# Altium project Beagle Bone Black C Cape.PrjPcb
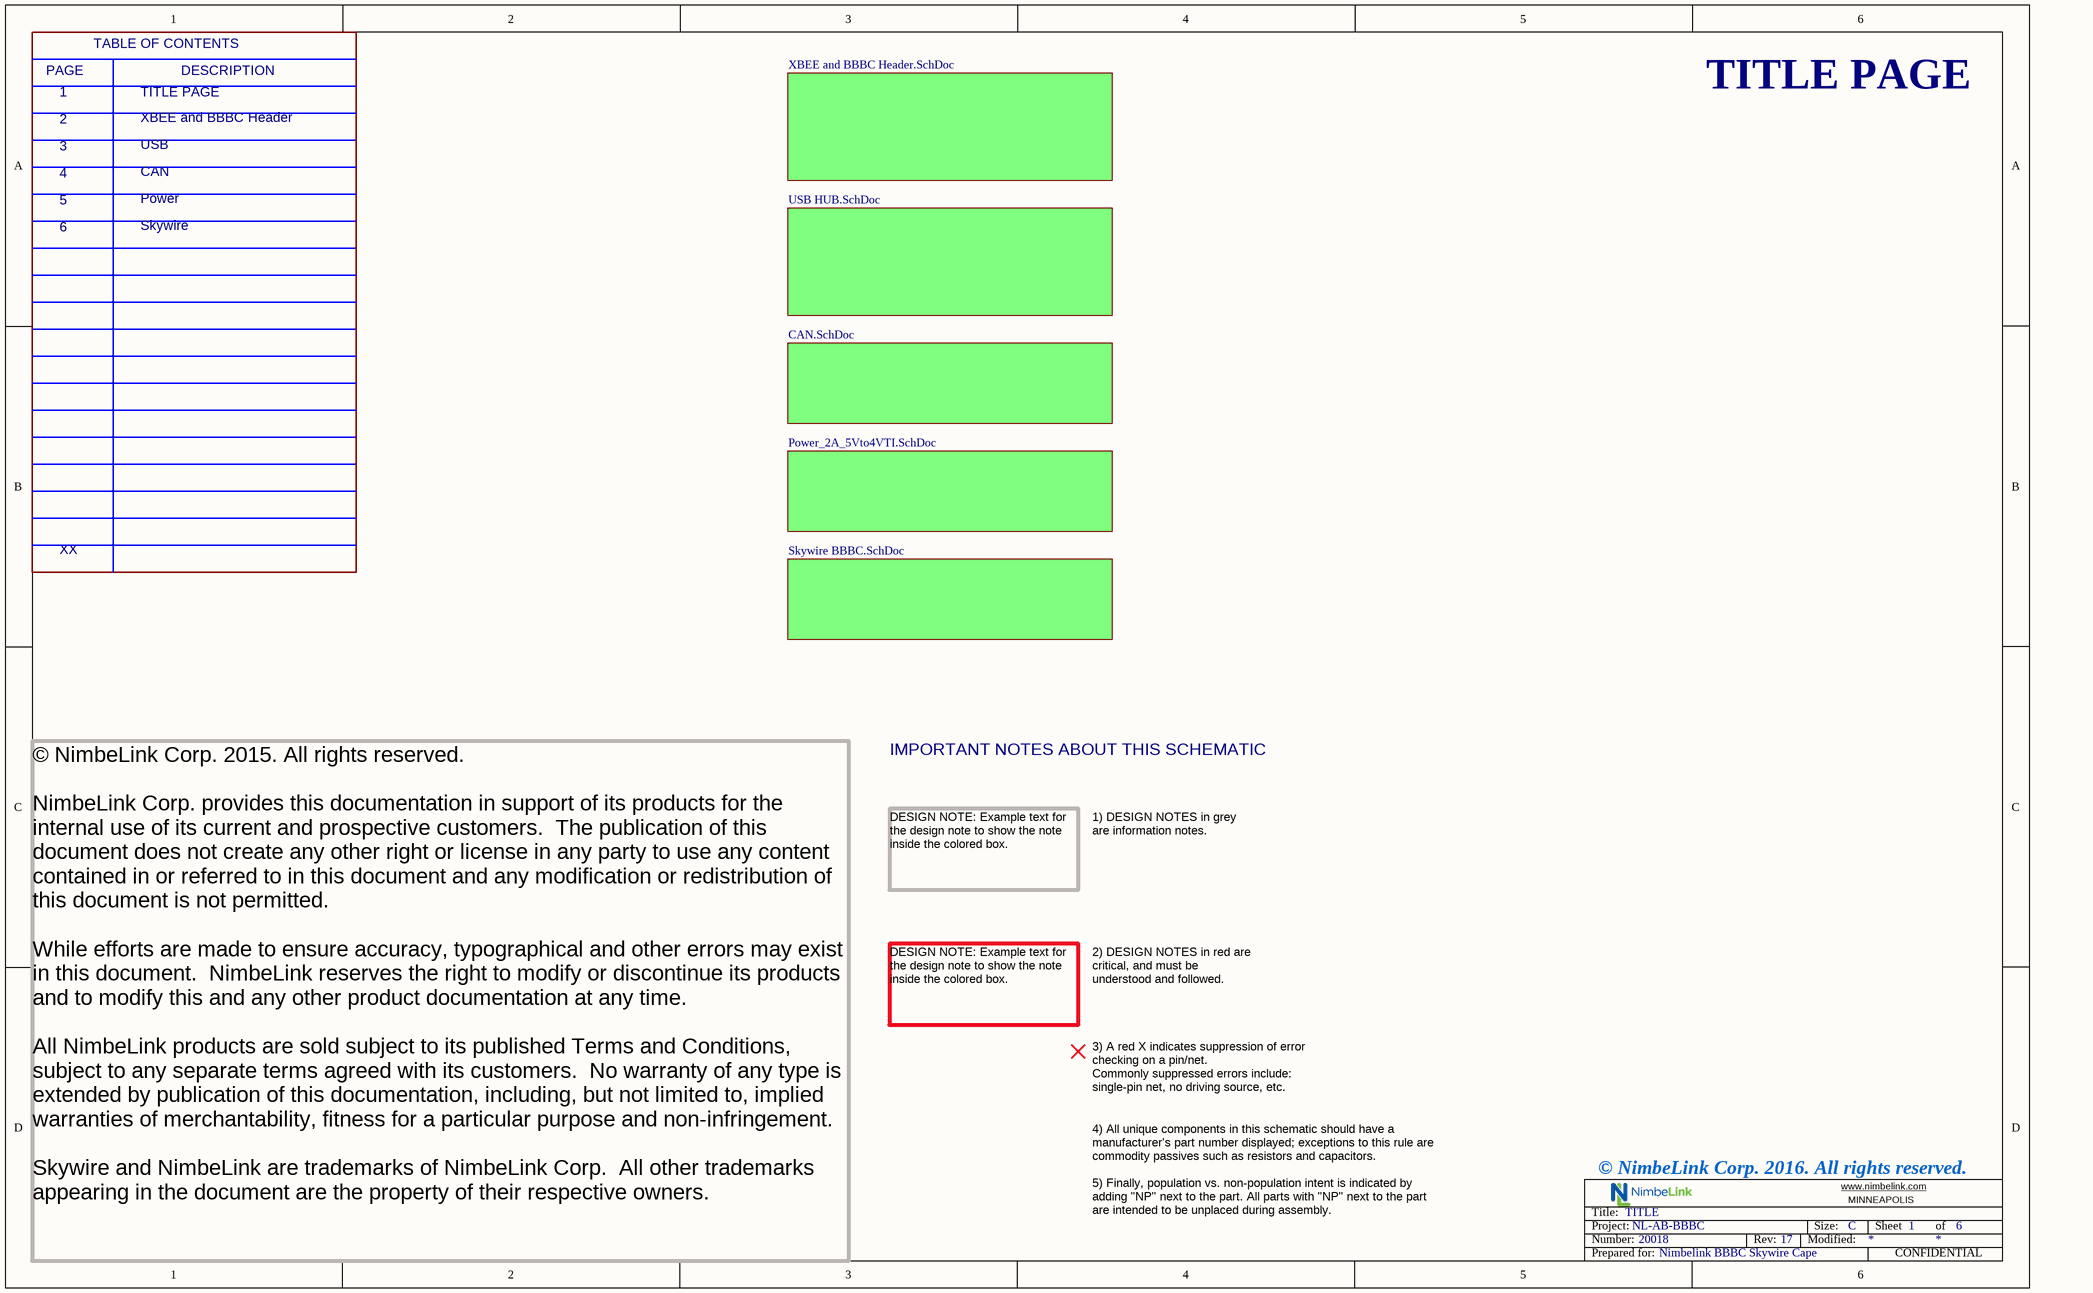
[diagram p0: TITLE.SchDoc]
NL_BILLING_CODE: NL-AB-BBBC; NL_SCH_PN: 20018; NL_SCH_REV: 17; NL_VERBOSE_CUST_NAME: Nimbelink BBBC Skywire Cape
6 sheets, 182 parts. Net scope: flat (ports and power ports of the same name join across sheets).
Board file: 20018REVE.PcbDoc
Sheets:
  TITLE.SchDoc
     = USB HUB.SchDoc
     = XBEE and BBBC Header.SchDoc
     = CAN.SchDoc
     = Power_2A_5Vto4VTI.SchDoc
     = Skywire BBBC.SchDoc

## Sheet TITLE.SchDoc: TITLE
size B; SheetNumber: 1; SheetTotal: 6

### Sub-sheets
? = USB HUB.SchDoc: no entries
? = XBEE and BBBC Header.SchDoc: no entries
? = CAN.SchDoc: no entries
? = Power_2A_5Vto4VTI.SchDoc: no entries
? = Skywire BBBC.SchDoc: no entries

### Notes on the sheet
- PAGE
- 1
- TABLE OF CONTENTS
- TITLE PAGE
- DESCRIPTION
- 2
- 3
- XBEE and BBBC Header
- USB
- 4
- 5
- 6
- Skywire
- Power
- CAN
- XX
- IMPORTANT NOTES ABOUT THIS SCHEMATIC
- DESIGN NOTE: Example text for the design note to show the note inside the colored box.
- 1) DESIGN NOTES in grey are information notes.
- 2) DESIGN NOTES in red are critical, and must be understood and followed.
- 3) A red X indicates suppression of error checking on a pin/net.
  Commonly suppressed errors include: single-pin net, no driving source, etc.
- © NimbeLink Corp. 2016. All rights reserved.
- 4) All unique components in this schematic should have a manufacturer's part number displayed; exceptions to this rule are commodity passives such as resistors and capacitors.
  5) Finally, population vs. non-population intent is indicated by adding "NP" next to the part. All parts with "NP" next to the part are intended to be unplaced during assembly.
- © NimbeLink Corp. 2015. All rights reserved.
  NimbeLink Corp. provides this documentation in support of its products for the internal use of its current and prospective customers.  The publication of this document does not create any other right or license in any party to use any content contained in or referred to in this document and any modification or redistribution of this document is not permitted.
  While efforts are made to ensure accuracy, typographical and other errors may exist in this document.  NimbeLink reserves the right to modify or discontinue its products and to modify this and any other product documentation at any time.
  All NimbeLink products are sold subject to its published Terms and Conditions, subject to any separate terms agreed with its customers.  No warranty of any type is extended by publication of this documentation, including, but not limited to, implied warranties of merchantability, fitness for a particular purpose and non-infringement.
  Skywire and NimbeLink are trademarks of NimbeLink Corp.  All other trademarks appearing in the document are the property of their respective owners.

## Sheet USB HUB.SchDoc: USB
size B; SheetNumber: 3; SheetTotal: 6
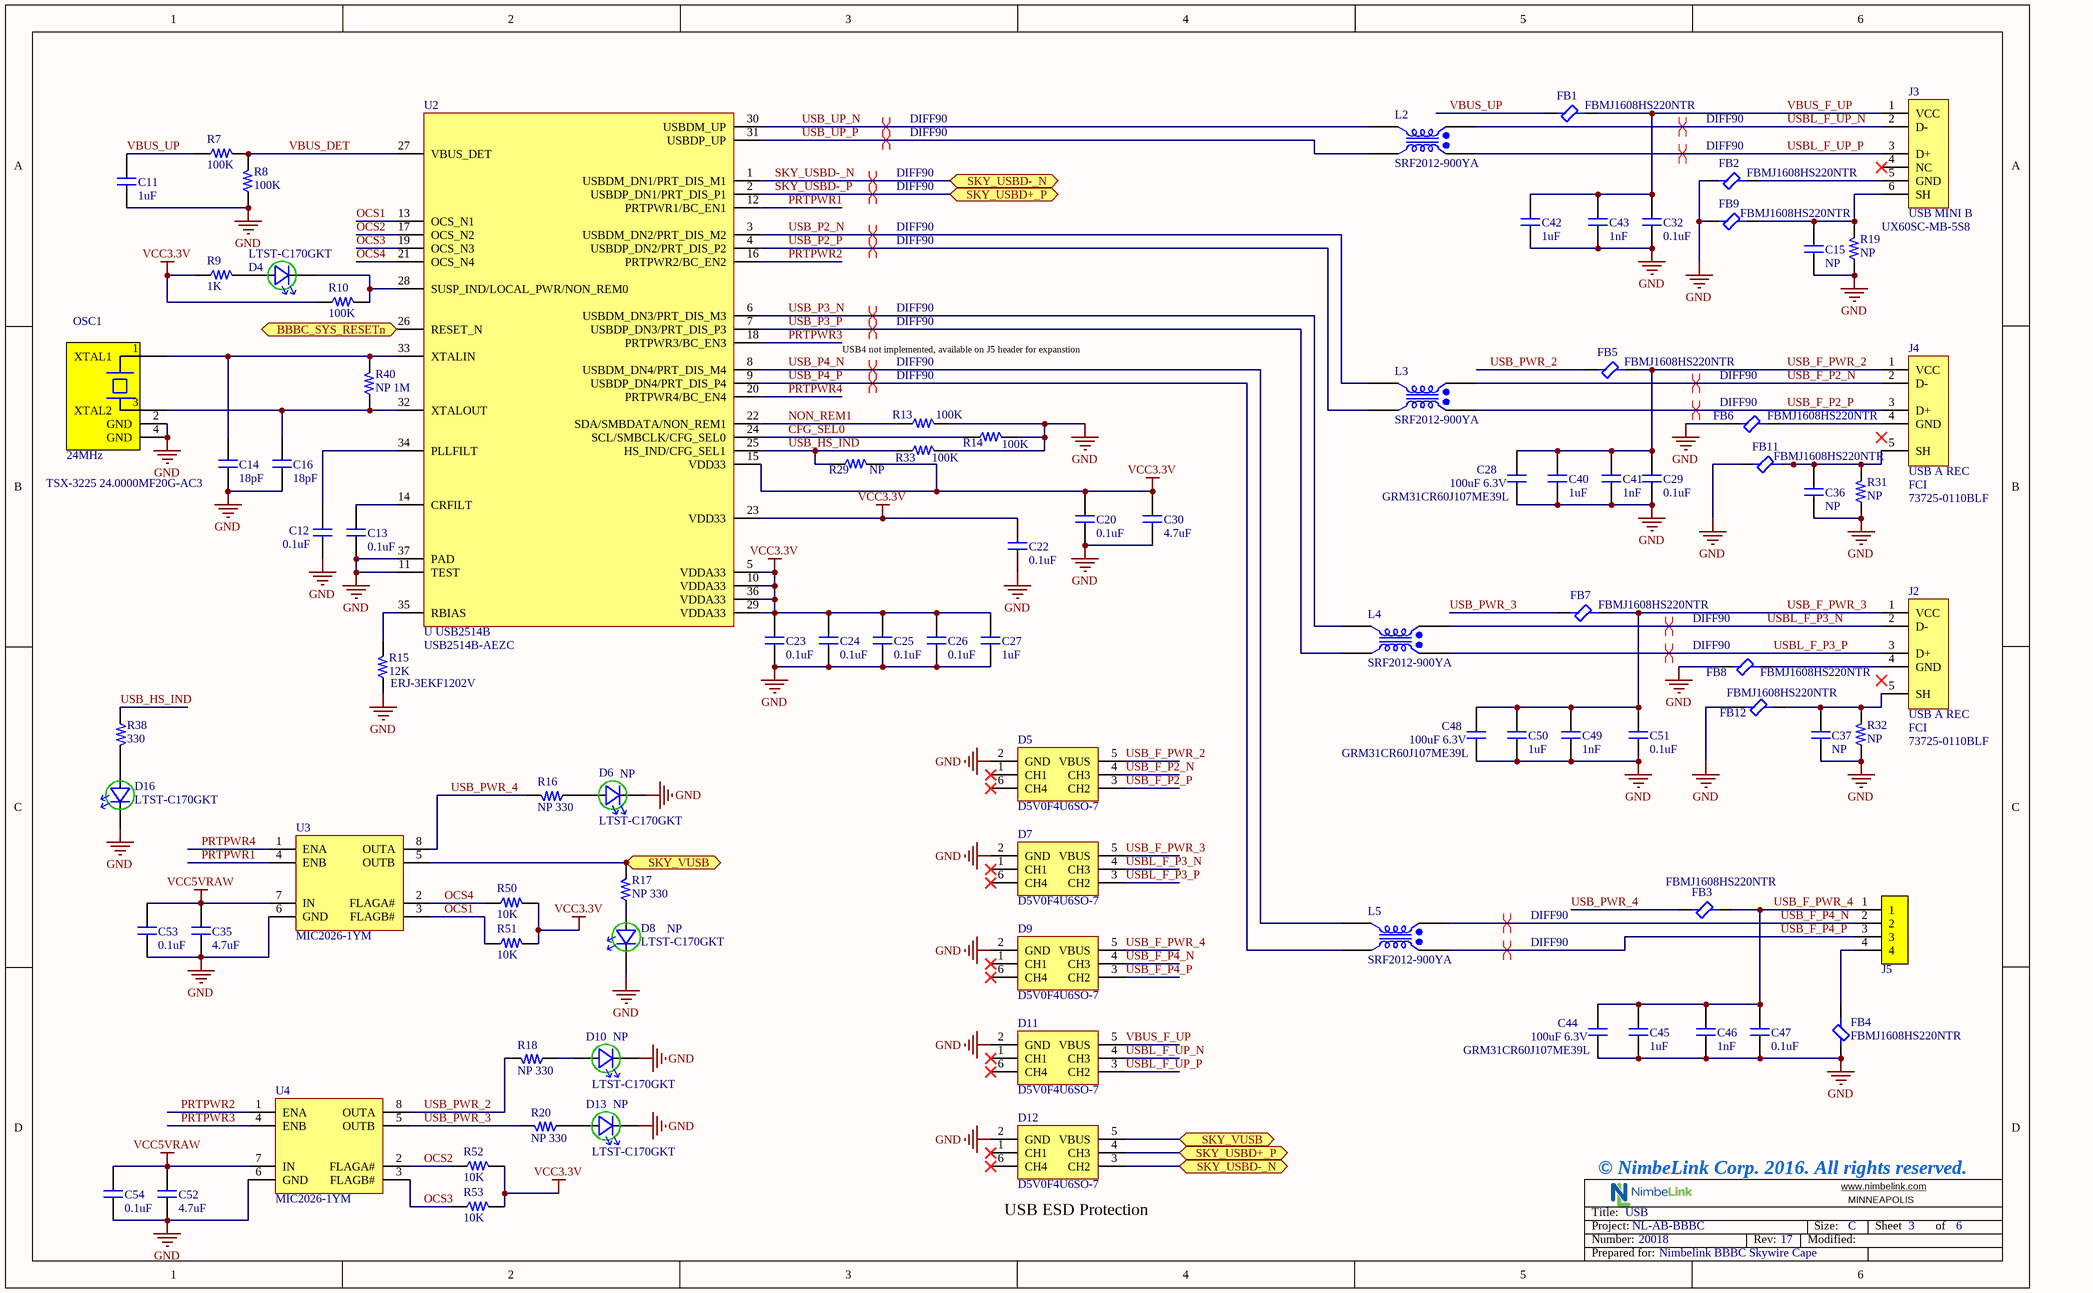
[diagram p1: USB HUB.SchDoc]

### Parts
C11  1uF  [0603]
C12  0.1uF  [0603]
C13  0.1uF  [0603]
C14  18pF  [0603]
C15  NP  [0603]
C16  18pF  [0603]
C20  0.1uF  [0603]
C22  0.1uF  [0603]
C23  0.1uF  [0603]
C24  0.1uF  [0603]
C25  0.1uF  [0603]
C26  0.1uF  [0603]
C27  1uF  [0603]
C28  100uF 6.3V  Manufacturer Part Number 1: GRM31CR60J107ME39L  [1206]
C29  0.1uF  [0603]
C30  4.7uF  [0603]
C32  0.1uF  [0603]
C35  4.7uF  [0603]
C36  NP  [0603]
C37  NP  [0603]
C40  1uF  [0603]
C41  1nF  [0603]
C42  1uF  [0603]
C43  1nF  [0603]
C44  100uF 6.3V  Manufacturer Part Number 1: GRM31CR60J107ME39L  [1206]
C45  1uF  [0603]
C46  1nF  [0603]
C47  0.1uF  [0603]
C48  100uF 6.3V  Manufacturer Part Number 1: GRM31CR60J107ME39L  [1206]
C49  1nF  [0603]
C50  1uF  [0603]
C51  0.1uF  [0603]
C52  4.7uF  [0603]
C53  0.1uF  [0603]
C54  0.1uF  [0603]
D4  Manufacturer Part Number 1: LTST-C170GKT  [D_LED_GREEN]  (hidden comment: D_LED_GREEN)
D5  D5V0F4U6SO-7  [D5V0F4U6SO-7]
D6  NP  Manufacturer Part Number 1: LTST-C170GKT  [D_LED_GREEN]
D7  D5V0F4U6SO-7  [D5V0F4U6SO-7]
D8  NP  Manufacturer Part Number 1: LTST-C170GKT  [D_LED_GREEN]
D9  D5V0F4U6SO-7  [D5V0F4U6SO-7]
D10  NP  Manufacturer Part Number 1: LTST-C170GKT  [D_LED_GREEN]
D11  D5V0F4U6SO-7  [D5V0F4U6SO-7]
D12  D5V0F4U6SO-7  [D5V0F4U6SO-7]
D13  NP  Manufacturer Part Number 1: LTST-C170GKT  [D_LED_GREEN]
D16  Manufacturer Part Number 1: LTST-C170GKT  [D_LED_GREEN]  (hidden comment: D_LED_GREEN)
FB1  Manufacturer Part Number 1: FBMJ1608HS220NTR  [0603]  (hidden comment: FB 7.5A 22Ohm 0.04DCR 0603)
FB2  Manufacturer Part Number 1: FBMJ1608HS220NTR  [0603]  (hidden comment: FB 7.5A 22Ohm 0.04DCR 0603)
FB3  Manufacturer Part Number 1: FBMJ1608HS220NTR  [0603]  (hidden comment: FB 7.5A 22Ohm 0.04DCR 0603)
FB4  Manufacturer Part Number 1: FBMJ1608HS220NTR  [0603]  (hidden comment: FB 7.5A 22Ohm 0.04DCR 0603)
FB5  Manufacturer Part Number 1: FBMJ1608HS220NTR  [0603]  (hidden comment: FB 7.5A 22Ohm 0.04DCR 0603)
FB6  Manufacturer Part Number 1: FBMJ1608HS220NTR  [0603]  (hidden comment: FB 7.5A 22Ohm 0.04DCR 0603)
FB7  Manufacturer Part Number 1: FBMJ1608HS220NTR  [0603]  (hidden comment: FB 7.5A 22Ohm 0.04DCR 0603)
FB8  Manufacturer Part Number 1: FBMJ1608HS220NTR  [0603]  (hidden comment: FB 7.5A 22Ohm 0.04DCR 0603)
FB9  Manufacturer Part Number 1: FBMJ1608HS220NTR  [0603]  (hidden comment: FB 7.5A 22Ohm 0.04DCR 0603)
FB11  Manufacturer Part Number 1: FBMJ1608HS220NTR  [0603]  (hidden comment: FB 7.5A 22Ohm 0.04DCR 0603)
FB12  Manufacturer Part Number 1: FBMJ1608HS220NTR  [0603]  (hidden comment: FB 7.5A 22Ohm 0.04DCR 0603)
J2  USB A REC  Manufacturer 1: FCI  Manufacturer Part Number 1: 73725-0110BLF  [USBA FCI VERT]
J3  USB MINI B  Manufacturer Part Number 1: UX60SC-MB-5S8  [USB MINI B]
J4  USB A REC  Manufacturer 1: FCI  Manufacturer Part Number 1: 73725-0110BLF  [USBA FCI VERT]
J5  NP  [HEADER 4PIN 2MMPITCH]  (value not drawn)
L2  SRF2012-900YA  [SRF2012-900YA]
L3  SRF2012-900YA  [SRF2012-900YA]
L4  SRF2012-900YA  [SRF2012-900YA]
L5  SRF2012-900YA  [SRF2012-900YA]
OSC1  24MHz  [OSC 008-0288-0_F]
R7  100K  [0603]
R8  100K  [0603]
R9  1K  [0603]
R10  100K  [0603]
R13  100K  [0603]
R14  100K  [0603]
R15  12K  Manufacturer Part Number 1: ERJ-3EKF1202V  [0603]
R16  NP 330  [0603]
R17  NP 330  [0603]
R18  NP 330  [0603]
R19  NP  [0603]
R20  NP 330  [0603]
R29  NP  [0603]
R31  NP  [0603]
R32  NP  [0603]
R33  100K  [0603]
R38  330  [0603]
R40  NP 1M  [0603]
R50  10K  [0603]
R51  10K  [0603]
R52  10K  [0603]
R53  10K  [0603]
U2  U USB2514B  Manufacturer Part Number 1: USB2514B-AEZC  [USB2514]
U3  Manufacturer Part Number 1: MIC2026-1YM  [MIC2026]  (hidden comment: U MIC2026)
U4  Manufacturer Part Number 1: MIC2026-1YM  [MIC2026]  (hidden comment: U MIC2026)

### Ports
BBBC_SYS_RESETn, SKY_USBD+_P, SKY_USBD-_N, SKY_VUSB

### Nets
GND: C11.2 C12.2 C13.2 C14.1 C15.2 C16.1 C20.2 C22.2 C23.2 C24.2 C25.2 C26.2 C27.2 C28.2 C29.2 C30.2 C32.2 C35.2 C36.2 C37.2 C40.2 C41.2 C42.2 C43.2 C44.2 C45.2 C46.2 C47.2 C48.2 C49.2 C50.2 C51.2 C52.2 C53.2 C54.2 D5.2(GND) D6.2(Cathode) D7.2(GND) D8.2(Cathode) D9.2(GND) D10.2(Cathode) D11.2(GND) D12.2(GND) D13.2(Cathode) D16.2(Cathode) FB2.1 FB4.1 FB6.1 FB8.1 FB9.1 FB11.1 FB12.1 OSC1.2(GND) OSC1.4(GND) R8.1 R13.2 R14.2 R15.1 R19.1 R31.1 R32.1 R33.2 U2.11(TEST) U2.37(PAD) U3.6(GND) U4.6(GND)
VCC3.3V: C20.1 C22.1 C23.1 C24.1 C25.1 C26.1 C27.1 C30.1 R9.1 R10.1 R29.2 R50.2 R51.2 R52.2 R53.2 U2.5(VDDA33) U2.10(VDDA33) U2.15(VDD33) U2.23(VDD33) U2.29(VDDA33) U2.36(VDDA33)
VCC5VRAW: C35.1 C52.1 C53.1 C54.1 U3.7(IN) U4.7(IN)
CFG_SEL0: R14.1 U2.24(SCL/SMBCLK/CFG_SEL0)
NON_REM1: R13.1 U2.22(SDA/SMBDATA/NON_REM1)
OCS1: R51.1 U2.13(OCS_N1) U3.3(FLAGB#)
OCS2: R52.1 U2.17(OCS_N2) U4.2(FLAGA#)
OCS3: R53.1 U2.19(OCS_N3) U4.3(FLAGB#)
OCS4: R50.1 U2.21(OCS_N4) U3.2(FLAGA#)
PRTPWR1: U2.12(PRTPWR1/BC_EN1) U3.4(ENB)
PRTPWR2: U2.16(PRTPWR2/BC_EN2) U4.1(ENA)
PRTPWR3: U2.18(PRTPWR3/BC_EN3) U4.4(ENB)
PRTPWR4: U2.20(PRTPWR4/BC_EN4) U3.1(ENA)
SKY_USBD-_N: D12.3(CH2) U2.1(USBDM_DN1/PRT_DIS_M1) ; port SKY_USBD-_N
SKY_USBD-_P: D12.4(CH3) U2.2(USBDP_DN1/PRT_DIS_P1) ; port SKY_USBD+_P
USB_F_P2_N: D5.4(CH3) J4.2(D-) L3.1
USB_F_P2_P: D5.3(CH2) J4.3(D+) L3.2
USB_F_P4_N: D9.4(CH3) J5.2 L5.1
USB_F_P4_P: D9.3(CH2) J5.3 L5.2
USB_F_PWR_2: C28.1 C29.1 C40.1 C41.1 D5.5(VBUS) FB5.2 J4.1(VCC)
USB_F_PWR_3: C48.1 C49.1 C50.1 C51.1 D7.5(VBUS) FB7.2 J2.1(VCC)
USB_F_PWR_4: C44.1 C45.1 C46.1 C47.1 D9.5(VBUS) FB3.2 J5.1
USB_HS_IND: R29.1 R33.1 R38.1 U2.25(HS_IND/CFG_SEL1)
USB_P2_N: L3.4 U2.3(USBDM_DN2/PRT_DIS_M2)
USB_P2_P: L3.3 U2.4(USBDP_DN2/PRT_DIS_P2)
USB_P3_N: L4.4 U2.6(USBDM_DN3/PRT_DIS_M3)
USB_P3_P: L4.3 U2.7(USBDP_DN3/PRT_DIS_P3)
USB_P4_N: L5.4 U2.8(USBDM_DN4/PRT_DIS_M4)
USB_P4_P: L5.3 U2.9(USBDP_DN4/PRT_DIS_P4)
USB_PWR_2: FB5.1 R18.2 U4.8(OUTA)
USB_PWR_3: FB7.1 R20.2 U4.5(OUTB)
USB_PWR_4: FB3.1 R16.2 U3.8(OUTA)
USB_UP_N: L2.4 U2.30(USBDM_UP)
USB_UP_P: L2.3 U2.31(USBDP_UP)
USBL_F_P3_N: D7.4(CH3) J2.2(D-) L4.1
USBL_F_P3_P: D7.3(CH2) J2.3(D+) L4.2
USBL_F_UP_N: D11.4(CH3) J3.2(D-) L2.1
USBL_F_UP_P: D11.3(CH2) J3.3(D+) L2.2
VBUS_DET: R7.2 R8.2 U2.27(VBUS_DET)
VBUS_F_UP: C32.1 C42.1 C43.1 D11.5(VBUS) FB1.2 J3.1(VCC)
VBUS_UP: C11.1 FB1.1 R7.1
NetC12_1: C12.1 U2.34(PLLFILT)
NetC13_1: C13.1 U2.14(CRFILT)
NetC14_2: C14.2 OSC1.1(XTAL1) R40.2 U2.33(XTALIN)
NetC15_1: C15.1 FB9.2 J3.6(SH) R19.2
NetC16_2: C16.2 OSC1.3(XTAL2) R40.1 U2.32(XTALOUT)
NetC17_1: U2.26(RESET_N) ; port BBBC_SYS_RESETn
NetC36_1: C36.1 FB11.2 J4.5(SH) R31.2
NetC37_1: C37.1 FB12.2 J2.5(SH) R32.2
NetD4_1: D4.1(Anode) R9.2
NetD4_2: D4.2(Cathode) R10.2 U2.28(SUSP_IND/LOCAL_PWR/NON_REM0)
NetD6_1: D6.1(Anode) R16.1
NetD8_1: D8.1(Anode) R17.1
NetD10_1: D10.1(Anode) R18.1
NetD12_5: D12.5(VBUS) R17.2 U3.5(OUTB) ; port SKY_VUSB
NetD13_1: D13.1(Anode) R20.1
NetD16_1: D16.1(Anode) R38.2
NetFB2_2: FB2.2 J3.5(GND)
NetFB4_2: FB4.2 J5.4
NetFB6_2: FB6.2 J4.4(GND)
NetFB8_2: FB8.2 J2.4(GND)
NetR15_2: R15.2 U2.35(RBIAS)

Not connected (* = marked no-connect by the designer): D5 1(CH1)* 6(CH4)*; D7 1(CH1)* 6(CH4)*; D9 1(CH1)* 6(CH4)*; D11 1(CH1)* 6(CH4)*; D12 1(CH1)* 6(CH4)*; J3 4(NC)*

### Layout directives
differential pair; net class DIFF90: SKY_USBD-_N, SKY_USBD-_P, USB_F_P2_N, USB_F_P2_P, USB_F_P4_N, USB_F_P4_P, USB_P2_N, USB_P2_P, USB_P3_N, USB_P3_P, USB_P4_N, USB_P4_P, USB_UP_N, USB_UP_P, USBL_F_P3_N, USBL_F_P3_P, USBL_F_UP_N, USBL_F_UP_P

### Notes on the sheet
- USB4 not implemented, available on J5 header for expanstion
- © NimbeLink Corp. 2016. All rights reserved.
- (near D12) USB ESD Protection

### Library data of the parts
C11 C27 C40 C42 C45 C50 = Cap 1uF 10V 10% X7R 0603 CER: Manufacturer Part Number 1: C1608X7R1A105K080AC; Type: Multilayer Ceramic Chip Capacitor; Brand: TDK; Case Length: 1.6 mm; Case Width: 0.8 mm
C12 C13 C20 C22-C26 C29 C32 C47 C51 C53 C54 = Cap 0.1uF 16V 10% X7R 0603 CER: Manufacturer 1: Samsung Electro-Mechanics America, Inc; Manufacturer Part Number 1: CL10B104KO8NNNC; Capacitance: 0.1µF
C14 C16 = Cap 18pF 100V 5% NP0 0603 CER: Manufacturer 1: Samsung Electro-Mechanics America, Inc; Manufacturer Part Number 1: CL10C180JC8NNNC; Temperature Coefficient: C0G, NP0
C15 C36 C37 = Cap
C28 C44 = Cap 100uF 6.3V 20% X5R 1206 CER: Manufacturer 1: Murata Electronics North America; Capacitance: 100µF
C30 C35 C52 = Cap 4.7UF 10V Y5V 0603: Manufacturer 1: Murata Electronics North America; Manufacturer Part Number 1: GRM188F51A475ZE20D; Capacitance: 4.7µF; Tolerance: -20%, +80%; Temperature Coefficient: Y5V (F)
C41 C43 C46 C49 = Cap 1nF 50V 10% X7R 0603 CER: Manufacturer 1: Murata Electronics North America; Manufacturer Part Number 1: GRM188R71H102KA01D; Capacitance: 1000pF
C48 = Cap 100uF 6.3V 20% X5R 1206 CER: Capacitance: 100µF
D4 D6 D8 D10 D13 D16 = D_LED_GREEN: LED GREEN  SMD; Lens Color/Style: Water Clear; Brand: Lite-On; Forward Current: 20 mA; Forward Voltage: 2.1 V; LED Size: 2 mm x 1.25 mm; Luminous Intensity: 6 mcd; Viewing Angle: 130 deg; Wavelength/Color Temperature: 569 nm
D5 D7 D9 D11 D12 = D TVS USB HIGH SPEED D5V0F4U6SO-7: USB ESD Protection D5V0F4U6SO-7; Manufacturer 1: Diodes Incorporated; Type: Steering (Rail to Rail); Bidirectional Channels: 4; Voltage - Reverse Standoff (Typ): 5.5V (Max); Voltage - Breakdown (Min): 6V; Voltage - Clamping (Max) @ Ipp: 12V; Current - Peak Pulse (10/1000µs): 1A (8/20µs); Power Line Protection: Yes; Capacitance @ Frequency: 0.5pF @ 1MHz
FB1-FB9 FB11 FB12 = FB 7.5A 22Ohm 0.04DCR 0603: Manufacturer 1: Taiyo Yuden; Impedance @ Frequency: 22 Ohm @ 100MHz; DC Resistance (DCR): 4 mOhm Max; Filter Type: Differential Mode - Single
J2 J4 = J USB A REC: Connector Type: USB - A; Number of Contacts: 4; Gender: Receptacle; Specifications: USB 2.0
J3 = J USB MINI B: Manufacturer 1: Hirose Electric Co Ltd; Connector Type: USB - mini B; Number of Contacts: 5; Gender: Receptacle; Specifications: USB 2.0
J5 = Header 4PIN 2mmpitch
L2-L5 = L USB Common Choke 90OHM SRF2012-900YA: Manufacturer 1: Bourns Inc.; Filter Type: Power or Data Line; Number of Lines: 2; Current: 400mA; DC Resistance (DCR): 300 mOhm Max; Impedance: 90 Ohm
OSC1 = CRYSTAL 24MHz 18pF: Manufacturer 1: CTS-Frequency Controls; Manufacturer Part Number 1: 403C35D24M00000; Frequency Stability: ±50ppm; Frequency Tolerance: ±30ppm; ESR (Equivalent Series Resistance): 60 Ohm; Operating Mode: Fundamental
R7 R8 R10 R13 R14 R33 = RES 100K 1/10W 1% 0603: Manufacturer 1: Samsung Electro-Mechanics America, Inc; Manufacturer Part Number 1: RC1608F104CS; Power (Watts): 0.1W, 1/10W; Temperature Coefficient: ±100ppm/°C
R9 = RES 1K 1/10W 1% 0603: Manufacturer 1: Stackpole Electronics Inc; Manufacturer Part Number 1: RNCP0603FTD1K00; Power (Watts): 0.125W, 1/8W; Temperature Coefficient: ±100ppm/°C
R15 = RES 12K 1/10W 1% 0603: Manufacturer 1: Panasonic Electronic Components; Power (Watts): 0.1W, 1/10W; Temperature Coefficient: ±100ppm/°C
R16-R18 R20 = RES 330 1/10W 1% 0603: Manufacturer 1: Panasonic Electronic Components; Manufacturer Part Number 1: ERJ-3GEYJ331V; Resistance (Ohms): 330; Tolerance: ±5%; Power (Watts): 0.1W, 1/10W; Temperature Coefficient: ±200ppm/°C
R19 R31 R32 = RES NP
R29 = R
R38 = RES 330 1/10W 1% 0603: Manufacturer 1: Panasonic Electronic Components; Manufacturer Part Number 1: ERJ-3GEYJ331V; Tolerance: ±5%; Power (Watts): 0.1W, 1/10W; Temperature Coefficient: ±200ppm/°C
R40 = RES 1M 1/10W 1% 0603: Power Rating: 100 mW; Resistance: 1 MOhms; Temperature Coefficient: - 400 PPM / C, + 150 PPM / C; Tolerance: 5 %; Voltage Rating: 75 V; Brand: Panasonic; Case Height: 0.45 mm; Case Length: 1.6 mm; Case Width: 0.8 mm
R50-R53 = RES 10K 1/10W 1% 0603: Power Rating: 100 mW; Resistance: 10 kOhms; Temperature Coefficient: 100 PPM / C; Voltage Rating: 75 V; Brand: Panasonic; Case Height: 0.45 mm; Case Length: 1.6 mm; Case Width: 0.8 mm
U2 = U USB2514B: Manufacturer 1: Microchip Technology; Protocol: USB; Function: Hub Controller; Voltage - Supply: 3 V ~ 3.6 V; Current - Supply: 70mA
U3 U4 = U MIC2026: Manufacturer 1: Micrel Inc; Number of Outputs: 2; Rds (On): 140 mOhm; Internal Switch(s): Yes; Current Limit: 900mA; Voltage - Input: 2.7 V ~ 5.5 V

## Sheet XBEE and BBBC Header.SchDoc: Xbee, BBBC Header, EEPROM, UART MUX
size B; SheetNumber: 2; SheetTotal: 6
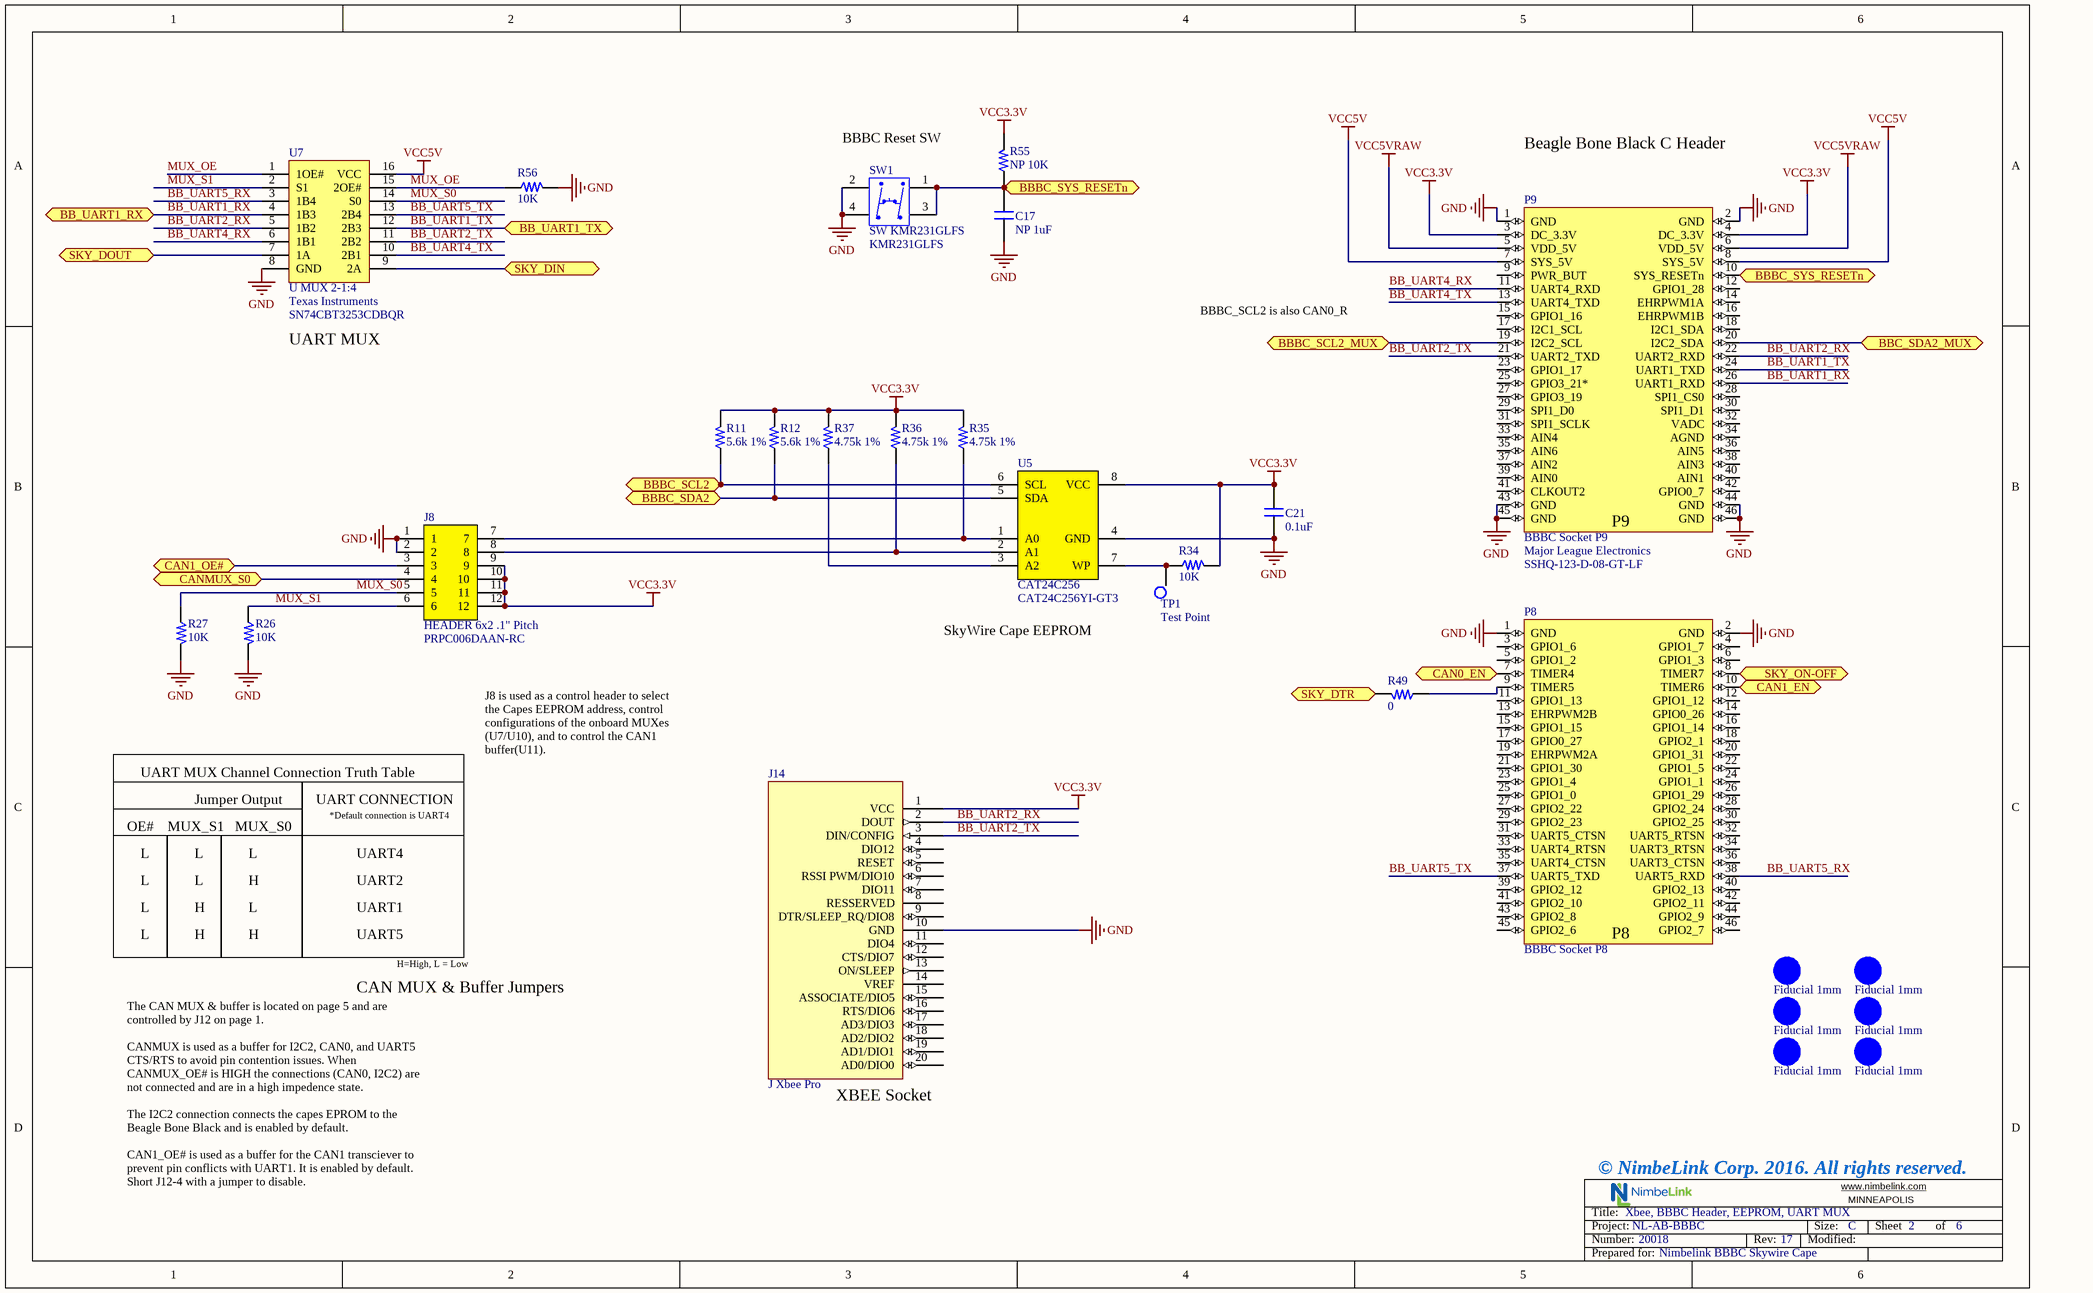
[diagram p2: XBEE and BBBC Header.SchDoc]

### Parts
C17  NP 1uF  [0603]
C21  0.1uF  [0603]
Fiducial1  Fiducial 1mm  [Fiducial 1mm]
Fiducial2  Fiducial 1mm  [Fiducial 1mm]
Fiducial3  Fiducial 1mm  [Fiducial 1mm]
Fiducial4  Fiducial 1mm  [Fiducial 1mm]
Fiducial5  Fiducial 1mm  [Fiducial 1mm]
Fiducial6  Fiducial 1mm  [Fiducial 1mm]
J8  HEADER 6x2 .1" Pitch  Manufacturer Part Number 1: PRPC006DAAN-RC  [HEADER 6x2 .1" Pitch]
J14  J Xbee Pro  [XbeePro RPSMA]
P8  BBBC Socket P8  [BBBC]
P9  BBBC Socket P9  Manufacturer: Major League Electronics  Manufacturer Part Number: SSHQ-123-D-08-GT-LF  [BBBC]
R11  5.6k 1%  [0603]
R12  5.6k 1%  [0603]
R26  10K  [0603]
R27  10K  [0603]
R34  10K  [0603]
R35  4.75k 1%  [0603]
R36  4.75k 1%  [0603]
R37  4.75k 1%  [0603]
R49  0  [0603]
R55  NP 10K  [0603]
R56  10K  [0603]
SW1  SW KMR231GLFS  [KMR231GLFS]
TP1  Test Point  [TP]
U5  CAT24C256  [TSSOP8 4.4x3 CASE 948AL-01]
U7  U MUX 2-1:4  Manufacturer 1: Texas Instruments  [SN74CBT3253CDBQR]

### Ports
BB_UART1_RX, BB_UART1_TX, BBBC_SCL2, BBBC_SCL2_MUX, BBBC_SDA2, BBBC_SYS_RESETn, BBC_SDA2_MUX, CAN0_EN, CAN1_EN, CAN1_OE#, CANMUX_S0, SKY_DIN, SKY_DOUT, SKY_DTR, SKY_ON-OFF

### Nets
GND: C17.2 C21.2 J8.1 J8.2 J14.10(GND) P8.1(GND) P8.2(GND) P9.1(GND) P9.2(GND) P9.43(GND) P9.44(GND) P9.45(GND) P9.46(GND) R26.1 R27.1 R56.2 SW1.2(WP) SW1.4(WP) U5.4(GND) U7.8(GND)
VCC3.3V: C21.1 J8.9 J8.10 J8.11 J8.12 J14.1(VCC) P9.3(DC_3.3V) P9.4(DC_3.3V) R11.2 R12.2 R34.2 R35.2 R36.2 R37.2 R55.2 U5.8(VCC)
VCC5V: P9.7(SYS_5V) P9.8(SYS_5V) U7.16(VCC)
VCC5VRAW: P9.5(VDD_5V) P9.6(VDD_5V)
BB_UART1_RX: P9.26(UART1_RXD) U7.4(1B3) ; port BB_UART1_RX
BB_UART1_TX: P9.24(UART1_TXD) U7.12(2B3) ; port BB_UART1_TX
BB_UART2_RX: J14.2(DOUT) P9.22(UART2_RXD) U7.5(1B2)
BB_UART2_TX: J14.3(DIN/CONFIG) P9.21(UART2_TXD) U7.11(2B2)
BB_UART4_RX: P9.11(UART4_RXD) U7.6(1B1)
BB_UART4_TX: P9.13(UART4_TXD) U7.10(2B1)
BB_UART5_RX: P8.38(UART5_RXD) U7.3(1B4)
BB_UART5_TX: P8.37(UART5_TXD) U7.13(2B4)
MUX_OE: R56.1 U7.1(1OE#) U7.15(2OE#)
MUX_S0: J8.5 R27.2 U7.14(S0)
MUX_S1: J8.6 R26.2 U7.2(S1)
NetC17_1: C17.1 P9.10(SYS_RESETn) R55.1 SW1.1(WP) SW1.3(WP) ; port BBBC_SYS_RESETn
NetJ6_2: U7.7(1A) ; port SKY_DOUT
NetJ6_3: U7.9(2A) ; port SKY_DIN
NetJ6_9: R49.2 ; port SKY_DTR
NetJ8_3: J8.3 ; port CAN1_OE#
NetJ8_4: J8.4 ; port CANMUX_S0
NetJ8_7: J8.7 R35.1 U5.1(A0)
NetJ8_8: J8.8 R36.1 U5.2(A1)
NetP8_7: P8.7(TIMER4) ; port CAN0_EN
NetP8_8: P8.8(TIMER7) ; port SKY_ON-OFF
NetP8_9: P8.9(TIMER5) R49.1
NetP8_10: P8.10(TIMER6) ; port CAN1_EN
NetP9_19: P9.19(I2C2_SCL) ; port BBBC_SCL2_MUX
NetP9_20: P9.20(I2C2_SDA) ; port BBC_SDA2_MUX
NetR11_1: R11.1 U5.6(SCL) ; port BBBC_SCL2
NetR12_1: R12.1 U5.5(SDA) ; port BBBC_SDA2
NetR34_1: R34.1 TP1.1(GND) U5.7(WP)
NetR37_1: R37.1 U5.3(A2)

Not connected (* = marked no-connect by the designer): J14 4(DIO12) 5(RESET) 6(RSSI_PWM/DIO10) 7(DIO11) 8(RESSERVED) 9(DTR/SLEEP_RQ/DIO8) 11(DIO4) 12(CTS/DIO7) 13(ON/SLEEP) 14(VREF) 15(ASSOCIATE/DIO5) 16(RTS/DIO6) 17(AD3/DIO3) 18(AD2/DIO2) 19(AD1/DIO1) 20(AD0/DIO0); P8 3(GPIO1_6) 4(GPIO1_7) 5(GPIO1_2) 6(GPIO1_3) 11(GPIO1_13) 12(GPIO1_12) 13(EHRPWM2B) 14(GPIO0_26) 15(GPIO1_15) 16(GPIO1_14) 17(GPIO0_27) 18(GPIO2_1) 19(EHRPWM2A) 20(GPIO1_31) 21(GPIO1_30) 22(GPIO1_5) 23(GPIO1_4) 24(GPIO1_1) 25(GPIO1_0) 26(GPIO1_29) 27(GPIO2_22) 28(GPIO2_24) 29(GPIO2_23) 30(GPIO2_25) 31(UART5_CTSN) 32(UART5_RTSN) 33(UART4_RTSN) 34(UART3_RTSN) 35(UART4_CTSN) 36(UART3_CTSN) 39(GPIO2_12) 40(GPIO2_13) 41(GPIO2_10) 42(GPIO2_11) 43(GPIO2_8) 44(GPIO2_9) 45(GPIO2_6) 46(GPIO2_7); P9 9(PWR_BUT) 12(GPIO1_28) 14(EHRPWM1A) 15(GPIO1_16) 16(EHRPWM1B) 17(I2C1_SCL) 18(I2C1_SDA) 23(GPIO1_17) 25(GPIO3_21*) 27(GPIO3_19) 28(SPI1_CS0) 29(SPI1_D0) 30(SPI1_D1) 31(SPI1_SCLK) 32(VADC) 33(AIN4) 34(AGND) 35(AIN6) 36(AIN5) 37(AIN2) 38(AIN3) 39(AIN0) 40(AIN1) 41(CLKOUT2) 42(GPIO0_7)

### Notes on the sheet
- (near SW1) BBBC Reset SW
- Beagle Bone Black C Header
- UART MUX
- BBBC_SCL2 is also CAN0_R
- SkyWire Cape EEPROM
- UART MUX Channel Connection Truth Table
- OE#
- MUX_S1
- Jumper Output
- MUX_S0
- UART CONNECTION
- *Default connection is UART4
- J8 is used as a control header to select the Capes EEPROM address, control configurations of the onboard MUXes (U7/U10), and to control the CAN1 buffer(U11).
- L
- H
- UART1
- UART2
- UART4
- UART5
- H=High, L = Low
- CAN MUX & Buffer Jumpers
- (near J14) XBEE Socket
- © NimbeLink Corp. 2016. All rights reserved.
- The CAN MUX & buffer is located on page 5 and are controlled by J12 on page 1.
  CANMUX is used as a buffer for I2C2, CAN0, and UART5 CTS/RTS to avoid pin contention issues. When CANMUX_OE# is HIGH the connections (CAN0, I2C2) are not connected and are in a high impedence state.
  The I2C2 connection connects the capes EPROM to the Beagle Bone Black and is enabled by default.
  CAN1_OE# is used as a buffer for the CAN1 transciever to prevent pin conflicts with UART1. It is enabled by default. Short J12-4 with a jumper to disable.

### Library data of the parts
C17 = Cap 1uF 10V 10% X7R 0603 CER: as C11 on sheet USB HUB
C21 = Cap 0.1uF 16V 10% X7R 0603 CER: as C12 on sheet USB HUB
Fiducial1-Fiducial6 = Fiducial
J8 = HEADER 6x2 .1" Pitch: Manufacturer 1: Sullins Connector Solutions; Connector Type: Header, Unshrouded; Number of Positions: 12; Number of Positions Loaded: All; Pitch: 0.100" (2.54mm)
J14 = J Xbee Pro: ZIGBEE-PRO W/RPSMA ANT; Manufacturer: Digi International; Manufacturer Part Number: XBP24BZ7SIT-004; Frequency: 2.4GHz; Data Rate - Maximum: 250kbps; Modulation or Protocol: 802.15.4 Zigbee; Power - Output: 18dBm; Sensitivity: -102dBm; Voltage - Supply: 2.7 V ~ 3.6 V; Current - Receiving: 47mA; Current - Transmitting: 205mA; Data Interface: PCB, Through Hole; Antenna Connector: RP-SMA
P8 = J BBBC SOCKET P8
P9 = J BBBC SOCKET P9
R11 R12 = RES 5.6k 1/10W 1% 0603: Manufacturer 1: Panasonic Electronic Components; Manufacturer Part Number 1: ERJ-3EKF5601V; Power (Watts): 0.1W, 1/10W; Temperature Coefficient: ±100ppm/°C
R26 R27 R34 R55 R56 = RES 10K 1/10W 1% 0603: as R50 on sheet USB HUB
R35-R37 = RES 4.75k 1/10W 1% 0603: Manufacturer 1: Panasonic Electronic Components; Manufacturer Part Number 1: ERJ-3EKF4751V; Power (Watts): 0.1W, 1/10W; Temperature Coefficient: ±100ppm/°C
R49 = RES 0 1/10W 1% 0603: Manufacturer 1: Panasonic Electronic Components; Manufacturer Part Number 1: ERJ-3GEY0R00V; Resistance (Ohms): 0.0; Tolerance: Jumper; Power (Watts): 0.1W, 1/10W
SW1 = SW KMR231GLFS: Manufacturer 1: C&K Components; Circuit: SPST-NO; Switch Function: Off-Mom; Contact Rating @ Voltage: 0.05A @ 32VDC; Actuator Type: Standard; Actuator Height off PCB, from Pins: 1.90mm; Actuator Orientation: Top Actuated; Outline: 4.60mm x 2.80mm; Illumination: Non-Illuminated; Operating Force: 300gf; Switch Travel: 0.25mm; Mechanical Life: 150,000 Cycles
U5 = CAT24C256: CAT24C256YI-GT3; Manufacturer 1: ON Semiconductor; Format - Memory: EEPROMs - Serial; Memory Type: EEPROM; Memory Size: 256K (32K x 8); Speed: 400kHz; Interface: I²C, 2-Wire Serial; Voltage - Supply: 1.8 V ~ 5.5 V
U7 = U MUX 2-1:4: Number of Channels: 1 Channel; On Resistance - Max: 12 Ohms; Number of Switches: 2; Operating Supply Current: 3 uA; Operating Supply Voltage: 4 V to 5.5 V; Propagation Delay Time: 0.15 ns; Switch Configuration: SPDT

## Sheet CAN.SchDoc: CAN
size B; SheetNumber: 4; SheetTotal: 6
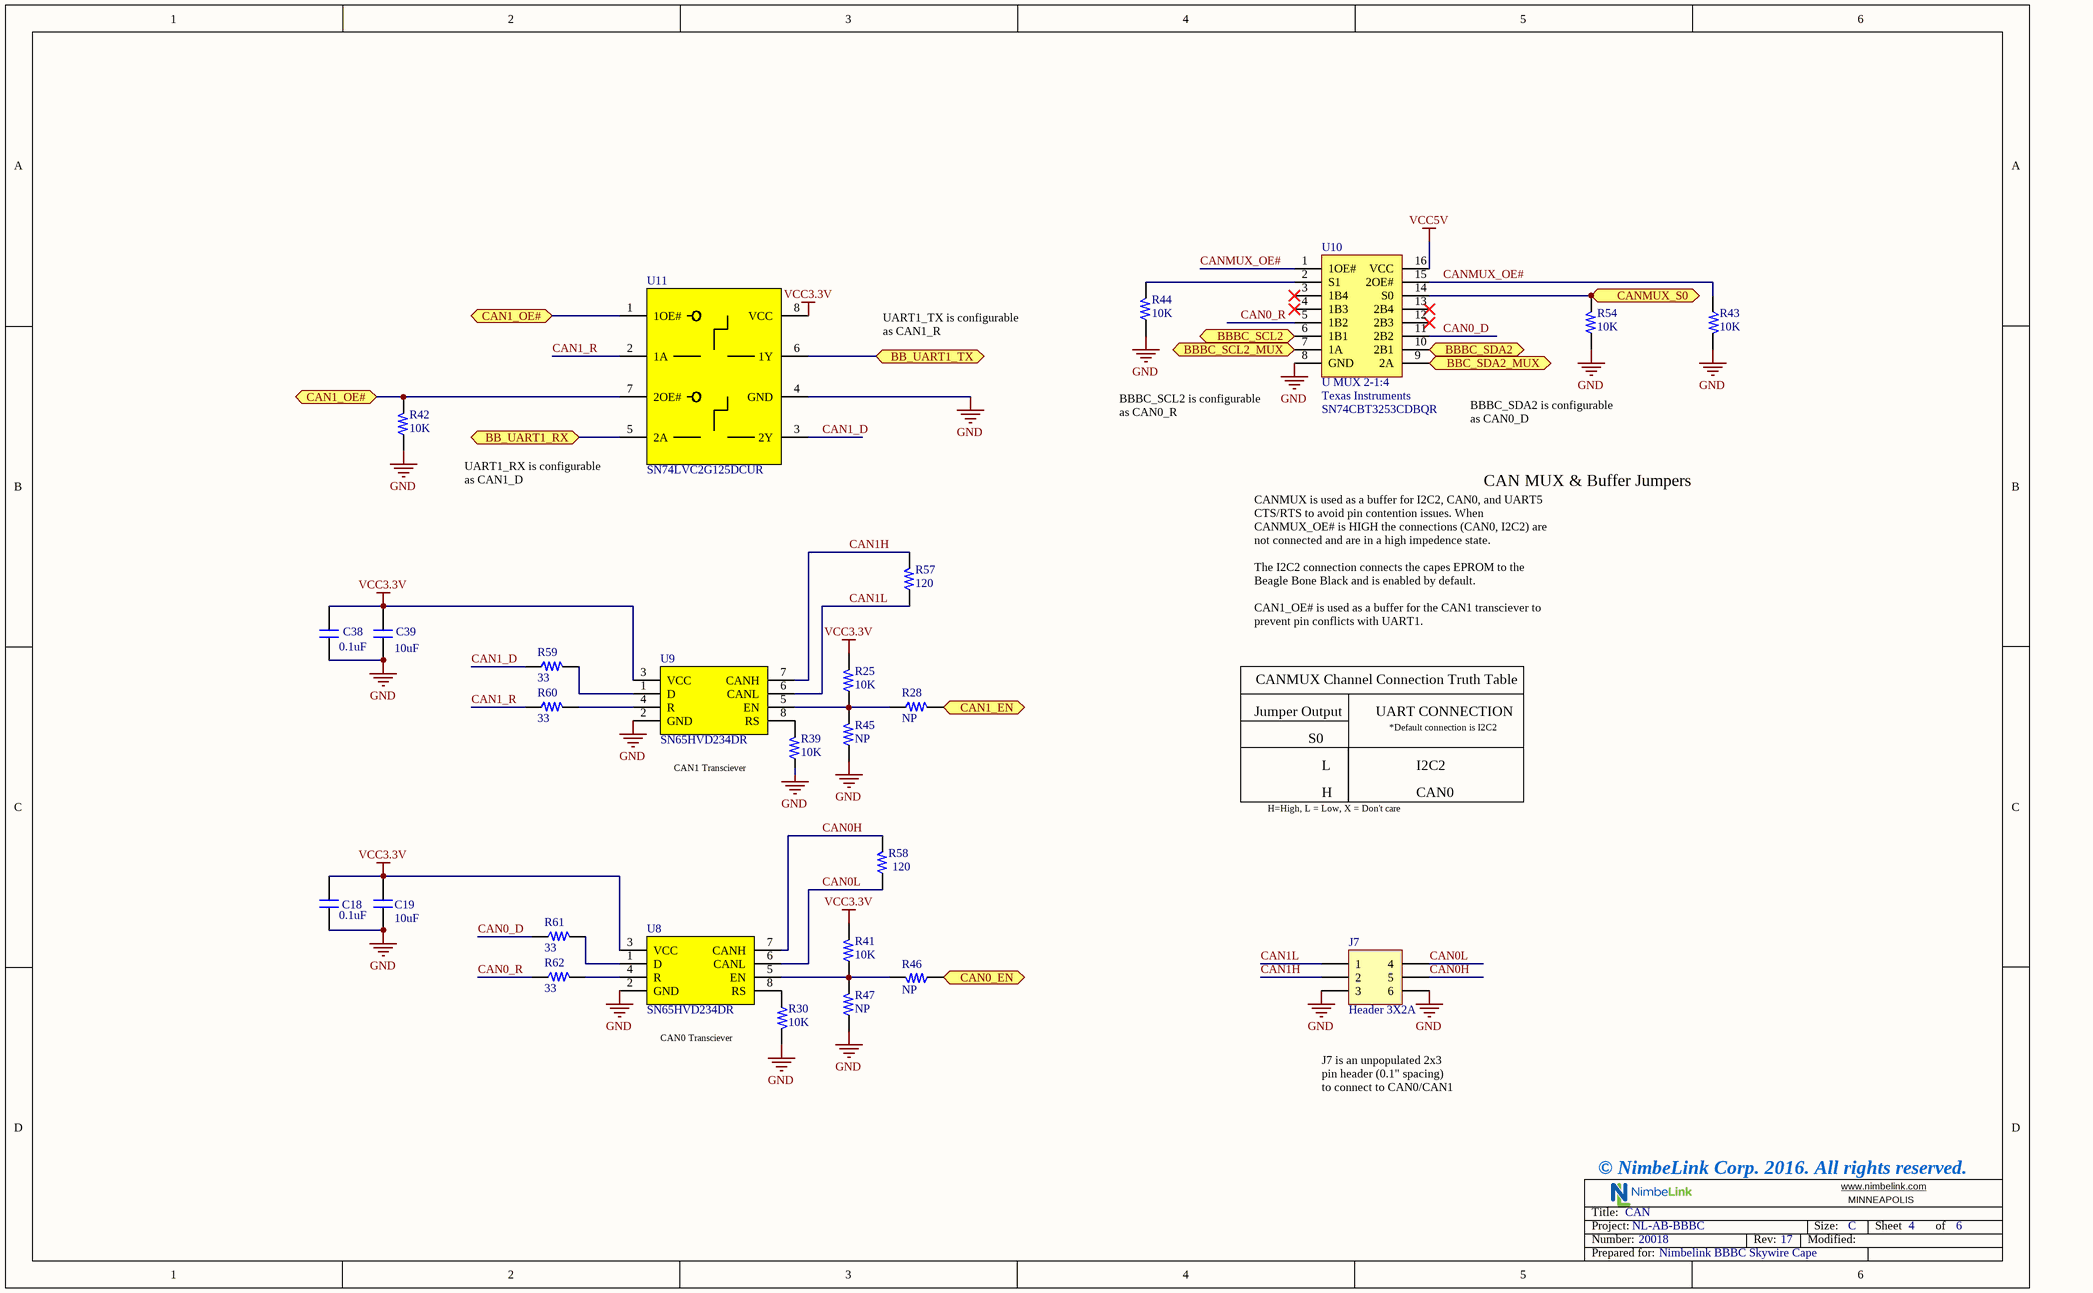
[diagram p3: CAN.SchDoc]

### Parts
C18  0.1uF  [0603]
C19  10uF  [0603]
C38  0.1uF  [0603]
C39  10uF  [0603]
J7  Header 3X2A  [HDR2X3_CEN]
R25  10K  [0603]
R28  NP  [0603]
R30  10K  [0603]
R39  10K  [0603]
R41  10K  [0603]
R42  10K  [0603]
R43  10K  [0603]
R44  10K  [0603]
R45  NP  [0603]
R46  NP  [0603]
R47  NP  [0603]
R54  10K  [0603]
R57  120  [0603]
R58  120  [0603]
R59  33  [0603]
R60  33  [0603]
R61  33  [0603]
R62  33  [0603]
U8  SN65HVD234DR  [SOIC8]
U9  SN65HVD234DR  [SOIC8]
U10  U MUX 2-1:4  Manufacturer 1: Texas Instruments  [SN74CBT3253CDBQR]
U11  U SN74LVC2G125  [SN74LVC2G125DCUR]  (value not drawn)

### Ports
BB_UART1_RX, BB_UART1_TX, BBBC_SCL2, BBBC_SCL2_MUX, BBBC_SDA2, BBC_SDA2_MUX, CAN0_EN, CAN1_EN, CAN1_OE#, CANMUX_S0

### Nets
GND: C18.2 C19.2 C38.2 C39.2 J7.3 J7.6 R30.2 R39.1 R42.2 R43.1 R44.2 R45.1 R47.1 R54.1 U8.2(GND) U9.2(GND) U10.8(GND) U11.4(GND)
VCC3.3V: C18.1 C19.1 C38.1 C39.1 R25.2 R41.2 U8.3(VCC) U9.3(VCC) U11.8(VCC)
VCC5V: U10.16(VCC)
BB_UART1_RX: U11.5(2A) ; port BB_UART1_RX
BB_UART1_TX: U11.6(1Y) ; port BB_UART1_TX
CAN0_D: R61.1 U10.11(2B2)
CAN0_R: R62.1 U10.5(1B2)
CAN0H: J7.5 R58.2 U8.7(CANH)
CAN0L: J7.4 R58.1 U8.6(CANL)
CAN1_D: R59.1 U11.3(2Y)
CAN1_R: R60.1 U11.2(1A)
CAN1H: J7.2 R57.2 U9.7(CANH)
CAN1L: J7.1 R57.1 U9.6(CANL)
CANMUX_OE#: R43.2 U10.1(1OE#) U10.15(2OE#)
NetJ8_3: R42.1 U11.1(1OE#) U11.7(2OE#) ; port CAN1_OE#
NetJ8_4: R54.2 U10.14(S0) ; port CANMUX_S0
NetP8_7: R46.1 ; port CAN0_EN
NetP8_10: R28.2 ; port CAN1_EN
NetP9_19: U10.7(1A) ; port BBBC_SCL2_MUX
NetP9_20: U10.9(2A) ; port BBC_SDA2_MUX
NetR11_1: U10.6(1B1) ; port BBBC_SCL2
NetR12_1: U10.10(2B1) ; port BBBC_SDA2
NetR25_1: R25.1 R28.1 R45.2 U9.5(EN)
NetR30_1: R30.1 U8.8(RS)
NetR39_2: R39.2 U9.8(RS)
NetR41_1: R41.1 R46.2 R47.2 U8.5(EN)
NetR44_1: R44.1 U10.2(S1)
NetR59_2: R59.2 U9.1(D)
NetR60_2: R60.2 U9.4(R)
NetR61_2: R61.2 U8.1(D)
NetR62_2: R62.2 U8.4(R)

Not connected (* = marked no-connect by the designer): U10 3(1B4)* 4(1B3)* 12(2B3)* 13(2B4)*

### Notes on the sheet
- UART1_TX is configurable as CAN1_R
- BBBC_SCL2 is configurable as CAN0_R
- BBBC_SDA2 is configurable as CAN0_D
- (near U11) UART1_RX is configurable as CAN1_D
- CAN MUX & Buffer Jumpers
- CANMUX is used as a buffer for I2C2, CAN0, and UART5 CTS/RTS to avoid pin contention issues. When CANMUX_OE# is HIGH the connections (CAN0, I2C2) are not connected and are in a high impedence state.
  The I2C2 connection connects the capes EPROM to the Beagle Bone Black and is enabled by default.
  CAN1_OE# is used as a buffer for the CAN1 transciever to prevent pin conflicts with UART1.
- CANMUX Channel Connection Truth Table
- CAN1 Transciever
- Jumper Output
- S0
- L
- UART CONNECTION
- *Default connection is I2C2
- I2C2
- H=High, L = Low, X = Don't care
- H
- CAN0
- CAN0 Transciever
- J7 is an unpopulated 2x3 pin header (0.1" spacing)  to connect to CAN0/CAN1
- © NimbeLink Corp. 2016. All rights reserved.

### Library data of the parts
C18 C38 = Cap 0.1uF 16V 10% X7R 0603 CER: as C12 on sheet USB HUB
C19 C39 = Cap 10uF 10V 10% X5R 0603 CER
J7 = Header 3X2A: Header, 3-Pin, Dual row
R25 R30 R39 R41-R44 R54 = RES 10K 1/10W 1% 0603: as R50 on sheet USB HUB
R28 R45-R47 = RES NP
R57 R58 = RES 120 1/10W 1% 0603
R59-R62 = RES 33 1/10W 1% 0603
U8 U9 = U SN65HVD234D: SN65HVD234D CAN Transciever; Manufacturer 1: Texas Instruments; Number of Drivers/Receivers: 1/1; Duplex: Half; Receiver Hysteresis: 100mV; Data Rate: 1Mbps; Voltage - Supply: 3 V ~ 3.6 V
U10 = U MUX 2-1:4: as U7 on sheet XBEE and BBBC Header
U11 = U SN74LVC2G125: Manufacturer 1: Texas Instruments; Logic Type: Buffer/Line Driver, Non-Inverting; Number of Elements: 2; Number of Bits per Element: 1; Current - Output High, Low: 32mA, 32mA; Voltage - Supply: 1.65 V ~ 5.5 V

## Sheet Power_2A_5Vto4VTI.SchDoc: Digital Power
size B; number: 20018; SheetNumber: 5; SheetTotal: 6
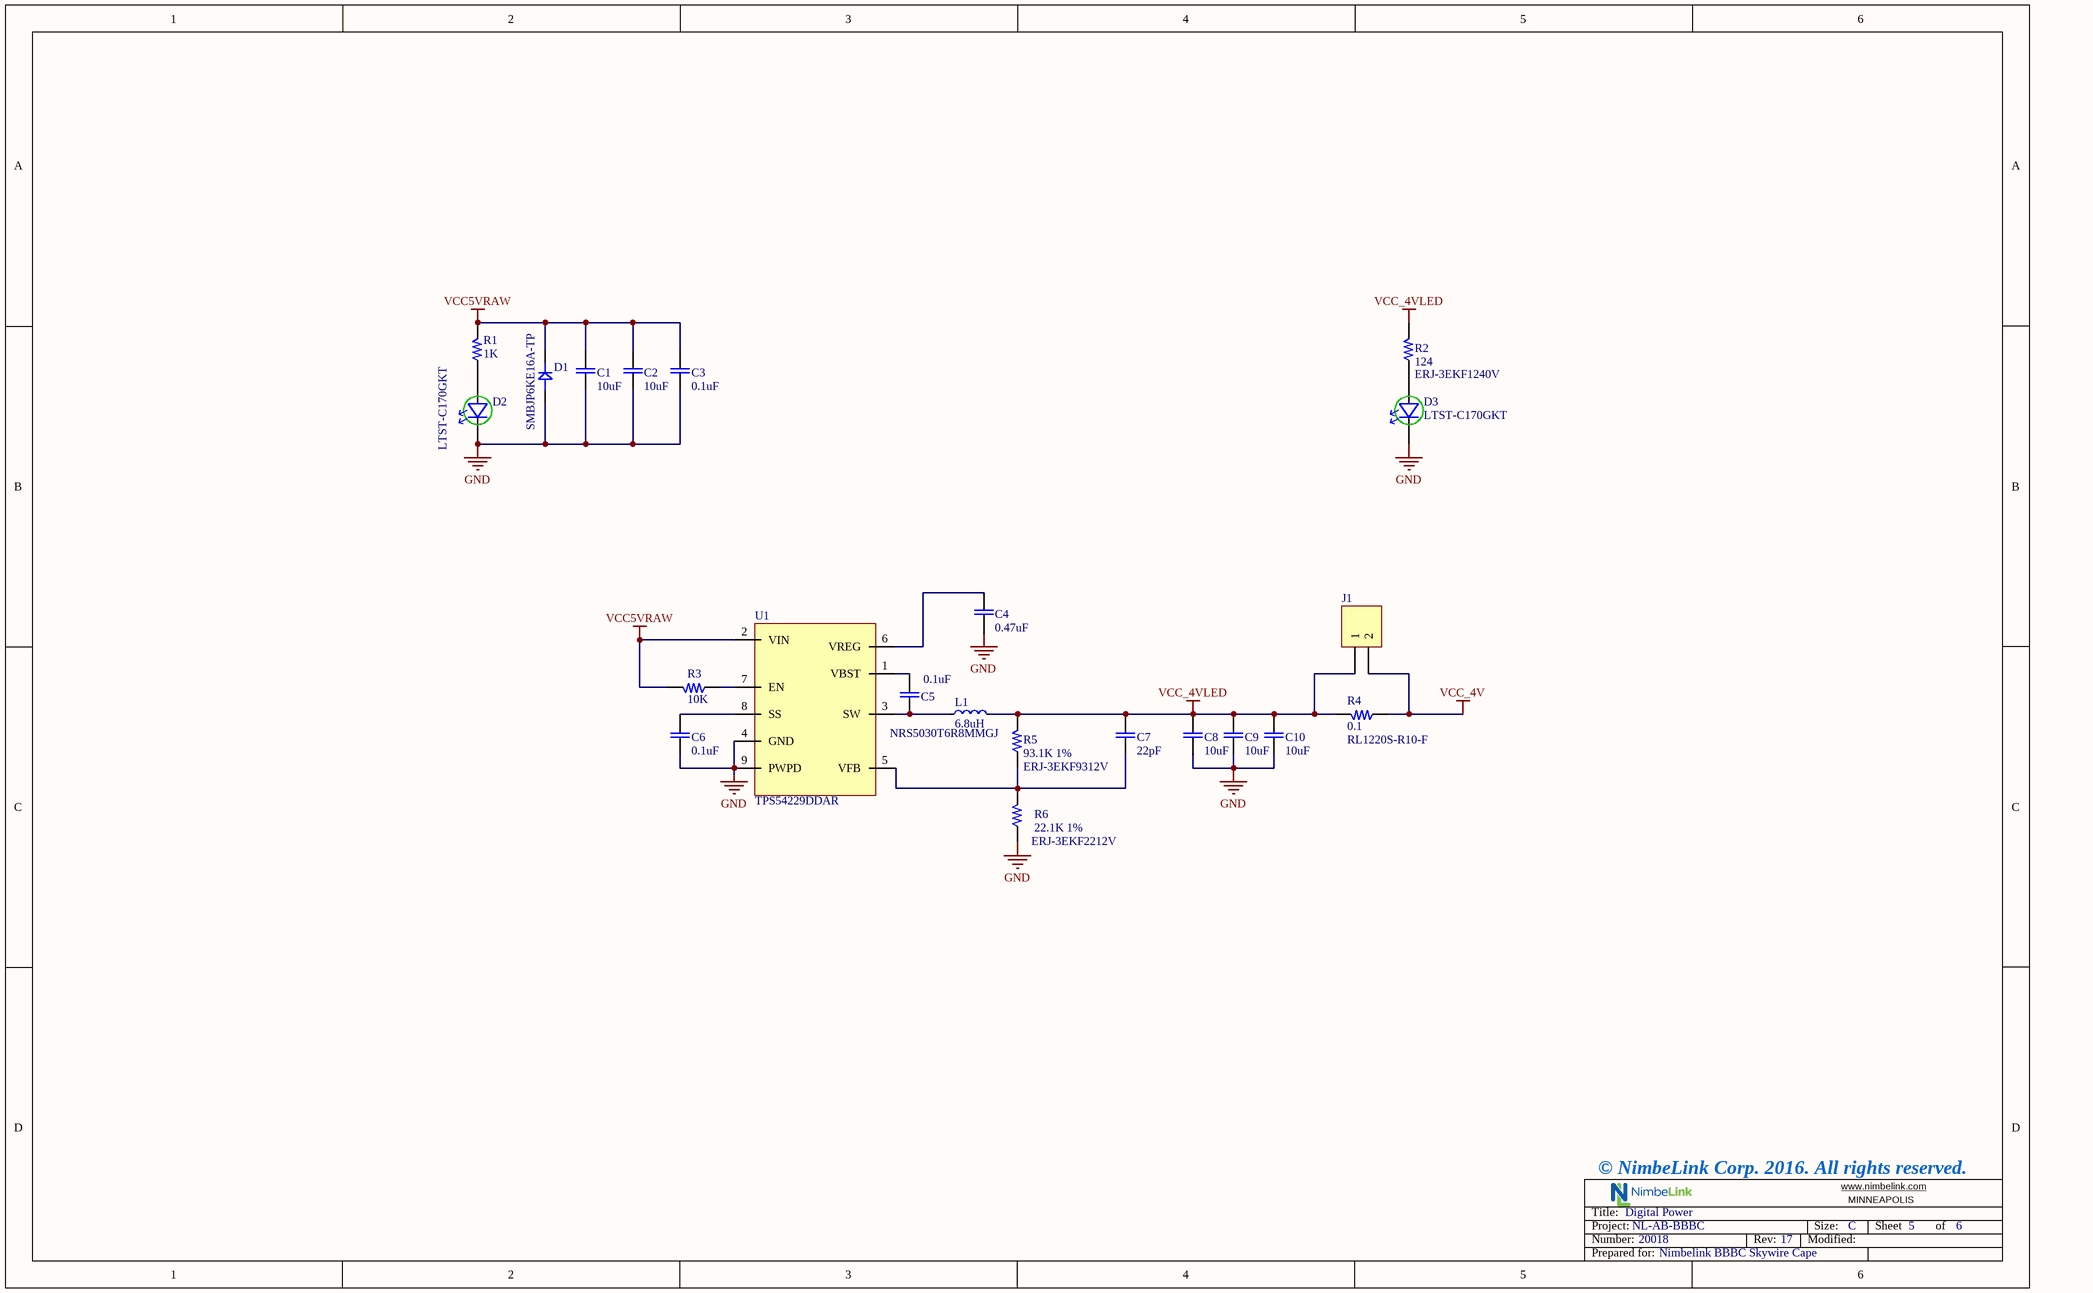
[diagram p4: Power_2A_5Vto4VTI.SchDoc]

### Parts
C1  10uF  [0603]
C2  10uF  [0603]
C3  0.1uF  [0603]
C4  0.47uF  [0603]
C5  0.1uF  [0603]
C6  0.1uF  [0603]
C7  22pF  [0603]
C8  10uF  [0603]
C9  10uF  [0603]
C10  10uF  [0603]
D1  Manufacturer Part Number 1: SMBJP6KE16A-TP  [D_SMBJP6KE16A-TP]  (hidden comment: D_TVS DIODE 13.6VWM 22.5VC SMBJ)
D2  Manufacturer Part Number 1: LTST-C170GKT  [D_LED_GREEN]  (hidden comment: D_LED_GREEN)
D3  Manufacturer Part Number 1: LTST-C170GKT  [D_LED_GREEN]  (hidden comment: D_LED_GREEN)
J1  NP  [HDR1X2]  (value not drawn)
L1  6.8uH  Manufacturer Part Number 1: NRS5030T6R8MMGJ  [NR5030]
R1  1K  [0603]
R2  124  Manufacturer Part Number 1: ERJ-3EKF1240V  [0603]
R3  10K  [0603]
R4  0.1  Manufacturer Part Number 2: RL1220S-R10-F  [0805]
R5  93.1K 1%  Manufacturer Part Number 1: ERJ-3EKF9312V  [0603]
R6  22.1K 1%  Manufacturer Part Number 1: ERJ-3EKF2212V  [0603]
U1  Manufacturer Part Number 1: TPS54229DDAR  [TPS54229DDA]  (hidden comment: U_TPS54229DDA)

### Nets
GND: C1.2 C2.2 C3.2 C4.1 C6.2 C8.2 C9.2 C10.2 D1.A D2.2(Cathode) D3.2(Cathode) R6.1 U1.4(GND) U1.9(PWPD)
VCC5VRAW: C1.1 C2.1 C3.1 D1.K R1.2 R3.2 U1.2(VIN)
VCC_4V: J1.2 R4.1
VCC_4VLED: C7.1 C8.1 C9.1 C10.1 J1.1 L1.2 R2.2 R4.2 R5.2
NetC4_2: C4.2 U1.6(VREG)
NetC5_1: C5.1 U1.1(VBST)
NetC5_2: C5.2 L1.1 U1.3(SW)
NetC6_1: C6.1 U1.8(SS)
NetC7_2: C7.2 R5.1 R6.2 U1.5(VFB)
NetD2_1: D2.1(Anode) R1.1
NetD3_1: D3.1(Anode) R2.1
NetR3_1: R3.1 U1.7(EN)

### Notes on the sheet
- © NimbeLink Corp. 2016. All rights reserved.

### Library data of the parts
C1 C2 C8-C10 = Cap 10uF 10V 10% X5R 0603 CER
C3 C5 C6 = Cap 0.1uF 16V 10% X7R 0603 CER
C4 = Cap 0.47uF 16V 10% X7R 0603 CER
C7 = Cap 22pF 50V 10% X7R 0603 CER: Manufactuer Part Number: 06035C220JAT2A
D1 = D_TVS DIODE 13.6VWM 22.5VC SMBJ: Breakdown Voltage: 16.8 V; Clamping Voltage: 22.5 V; Brand: Micro Commercial Components (MCC); Peak Surge Current: 27.1 A; Peak Pulse Power Dissipation: 600 W; Polarity: Unidirectional
D2 D3 = D_LED_GREEN: as D4 on sheet USB HUB
J1 = Header 2: Header, 2-Pin
L1 = L 6.8UH 2.3A 30% SMD NRS5030T6R8MMGJ: INDUCTOR 6.8UH 2.3A 30% SMD5030; Manufacturer 1: Taiyo Yuden; Inductance: 6.8µH; Tolerance: ±20%; Current - Saturation: 2.5A; Shielding: Shielded; DC Resistance (DCR): 52 mOhm; Frequency - Self Resonant: 22MHz; Frequency - Test: 100kHz
R1 = RES 1K 1/10W 1% 0603: as R9 on sheet USB HUB
R2 = RES 124 1/10W 1% 0603: Power Rating: 100 mW; Resistance: 124 Ohms; Voltage Rating: 75 V; Brand: Panasonic; Case Height: 0.45 mm; Case Length: 1.6 mm; Case Width: 0.8 mm
R3 = RES 10K 1/10W 1% 0603: as R50 on sheet USB HUB
R4 = RES 0.1 1/3W 1% 0805: Power Rating: 250 mW (1/4 W); Resistance: 100 mOhms; Temperature Coefficient: 200 PPM / C; Brand: Susumu; Case Height: 0.4 mm; Case Length: 2 mm; Case Width: 1.25 mm
R5 = RES 93.1K 1% 1/10W 0603: Power Rating: 100 mW; Resistance: 93.1 kOhms; Temperature Coefficient: 100 PPM / C; Voltage Rating: 75 V; Brand: Panasonic; Case Height: 0.45 mm; Case Length: 1.6 mm; Case Width: 0.8 mm
R6 = RES 22.1K 1/10W 1% 0603 SMD: Power Rating: 100 mW; Resistance: 22.1 kOhms; Temperature Coefficient: 100 PPM / C; Voltage Rating: 75 V; Brand: Panasonic; Case Height: 0.45 mm; Case Length: 1.6 mm; Case Width: 0.8 mm
U1 = U_TPS54229DDA: TPS54229DDA 4.5V-18V 2A; Manufacturer 1: Texas Instruments; Output Type: Adjustable; Number of Outputs: 1; Voltage - Output: 0.76 V ~ 7 V; Voltage - Input: 4.5 V ~ 18 V; PWM Type: Hybrid; Frequency - Switching: 700kHz; Synchronous Rectifier: Yes

## Sheet Skywire BBBC.SchDoc: Skywire Module
size B; SheetNumber: 6; SheetTotal: 6
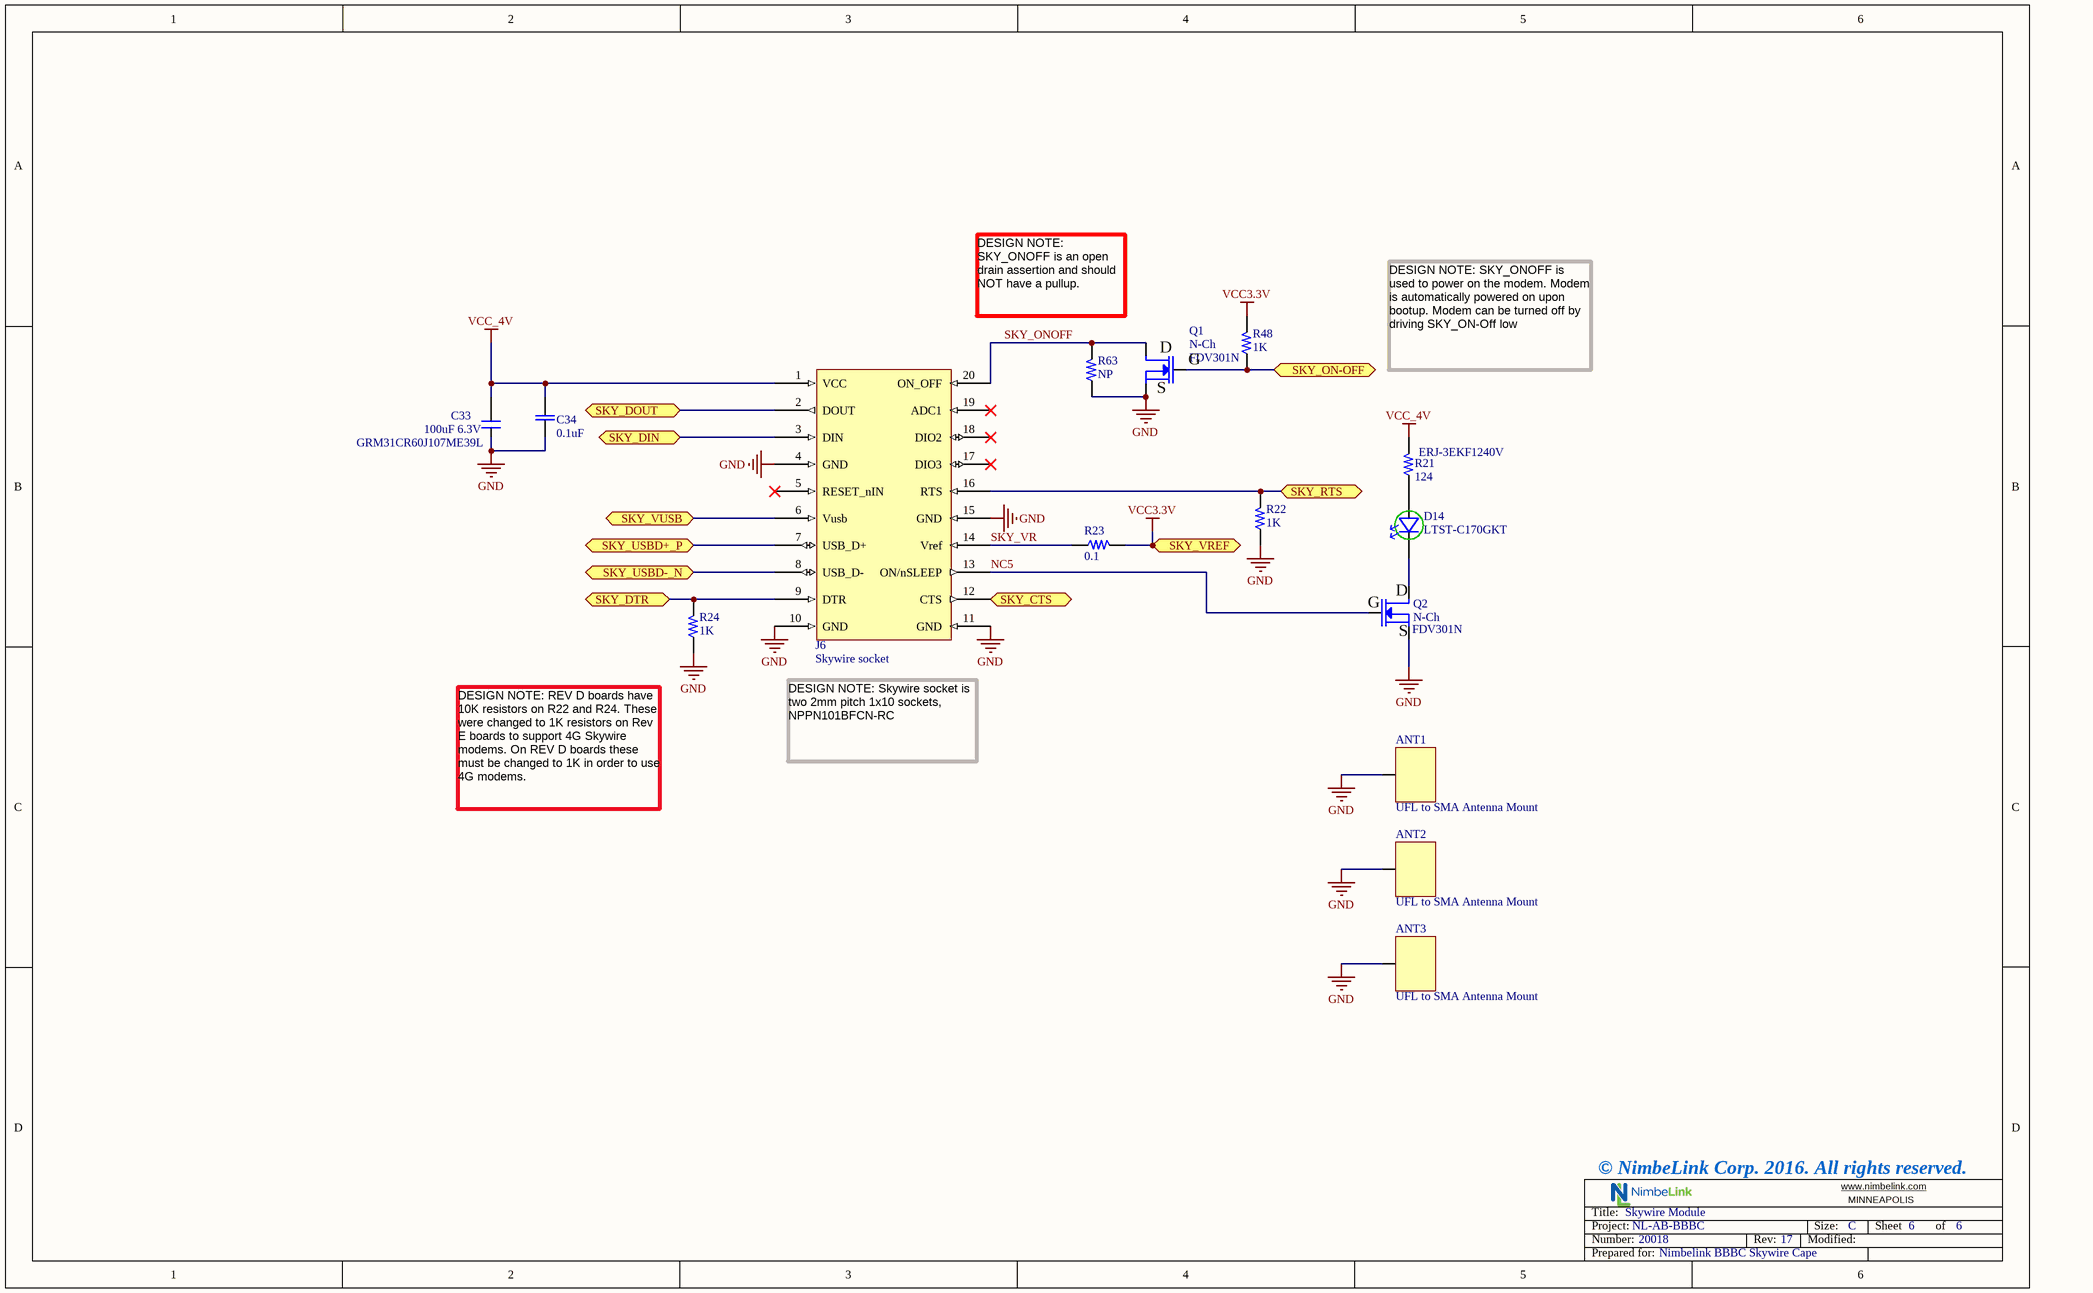
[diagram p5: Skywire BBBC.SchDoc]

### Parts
ANT1  UFL to SMA Antenna Mount  [UFL TO SMA]
ANT2  UFL to SMA Antenna Mount  [UFL TO SMA]
ANT3  UFL to SMA Antenna Mount  [UFL TO SMA]
C33  100uF 6.3V  Manufacturer Part Number 1: GRM31CR60J107ME39L  [1206]
C34  0.1uF  [0603]
D14  Manufacturer Part Number 1: LTST-C170GKT  [D_LED_GREEN]  (hidden comment: D_LED_GREEN)
J6  Skywire socket  [SKYWIRE SOCKET]
Q1  N-Ch  Manufacturer Part Number 2: FDV301N  [SOT-23-3]
Q2  N-Ch  Manufacturer Part Number 2: FDV301N  [SOT-23-3]
R21  124  Manufacturer Part Number 1: ERJ-3EKF1240V  [0603]
R22  1K  [0603]
R23  0.1  [0805]
R24  1K  [0603]
R48  1K  [0603]
R63  NP  [0603]

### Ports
SKY_CTS, SKY_DIN, SKY_DOUT, SKY_DTR, SKY_ON-OFF, SKY_RTS, SKY_USBD+_P, SKY_USBD-_N, SKY_VREF, SKY_VUSB

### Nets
GND: ANT1.1 ANT2.1 ANT3.1 C33.2 C34.2 J6.4(GND) J6.10(GND) J6.11(GND) J6.15(GND) Q1.3(S) Q2.3(S) R22.1 R24.1 R63.1
VCC3.3V: R23.2 R48.2 ; port SKY_VREF
VCC_4V: C33.1 C34.1 J6.1(VCC) R21.2
NC5: J6.13(ON/nSLEEP) Q2.1(G)
SKY_ONOFF: J6.20(ON_OFF) Q1.2(D) R63.2
SKY_USBD-_N: J6.8(USB_D-) ; port SKY_USBD-_N
SKY_USBD-_P: J6.7(USB_D+) ; port SKY_USBD+_P
SKY_VR: J6.14(Vref) R23.1
NetD12_5: J6.6(Vusb) ; port SKY_VUSB
NetD14_1: D14.1(Anode) R21.1
NetD14_2: D14.2(Cathode) Q2.2(D)
NetJ6_2: J6.2(DOUT) ; port SKY_DOUT
NetJ6_3: J6.3(DIN) ; port SKY_DIN
NetJ6_9: J6.9(DTR) R24.2 ; port SKY_DTR
NetJ6_12: J6.12(CTS) ; port SKY_CTS
NetJ6_16: J6.16(RTS) R22.2 ; port SKY_RTS
NetP8_8: Q1.1(G) R48.1 ; port SKY_ON-OFF

Not connected (* = marked no-connect by the designer): J6 5(RESET_nIN)* 17(DIO3)* 18(DIO2)* 19(ADC1)*

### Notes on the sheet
- DESIGN NOTE:
  SKY_ONOFF is an open drain assertion and should NOT have a pullup.
- DESIGN NOTE: SKY_ONOFF is used to power on the modem. Modem is automatically powered on upon bootup. Modem can be turned off by driving SKY_ON-Off low
- DESIGN NOTE: Skywire socket is two 2mm pitch 1x10 sockets, NPPN101BFCN-RC
- DESIGN NOTE: REV D boards have 10K resistors on R22 and R24. These were changed to 1K resistors on Rev E boards to support 4G Skywire modems. On REV D boards these must be changed to 1K in order to use 4G modems.
- © NimbeLink Corp. 2016. All rights reserved.

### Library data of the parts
ANT1-ANT3 = MTG UFL to SMA: Antenna Socket
C33 = Cap 100uF 6.3V 20% X5R 1206 CER: as C28 on sheet USB HUB
C34 = Cap 0.1uF 16V 10% X7R 0603 CER: as C12 on sheet USB HUB
D14 = D_LED_GREEN: as D4 on sheet USB HUB
J6 = Skywire socket: Manufacturer 1: Sullins Connector Solutions; Manufacturer Part Number 1: NPPN101BFCN-RC; Connector Type: Header; Number of Positions: 10; Number of Positions Loaded: All; Pitch: 0.079" (2.00mm)
Q1 Q2 = Q MOSFET N-CH 25V 220MA SOT-23: MOSFET N-CH 25V 220MA SOT-23; Configuration: Single; Brand: Fairchild Semiconductor; Forward Transconductance - Min: 0.2 S; Transistor Polarity: N-Channel; Channel Mode: Enhancement; Fall Time: 6 ns; Pd - Power Dissipation: 0.35 W; Rds On - Drain-Source Resistance: 5 Ohms; Typical Turn-Off Delay Time: 3.5 ns; Vgs - Gate-Source Breakdown Voltage: 8 V
R21 = RES 124 1/10W 1% 0603: as R2 on sheet Power_2A_5Vto4VTI
R22 R24 R48 = RES 1K 1/10W 1% 0603: as R9 on sheet USB HUB
R23 = RES 0.1 1/3W 1% 0805: as R4 on sheet Power_2A_5Vto4VTI
R63 = RES NP

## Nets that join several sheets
GND: USB HUB (66 pins), XBEE and BBBC Header (20 pins), CAN (18 pins), Power_2A_5Vto4VTI (14 pins), Skywire BBBC (14 pins)
VCC3.3V: USB HUB (21 pins), XBEE and BBBC Header (16 pins), CAN (9 pins), Skywire BBBC (R23.2 R48.2)
VCC5V: XBEE and BBBC Header (P9.7 P9.8 U7.16), CAN (U10.16)
VCC5VRAW: USB HUB (6 pins), XBEE and BBBC Header (P9.5 P9.6), Power_2A_5Vto4VTI (7 pins)
VCC_4V: Power_2A_5Vto4VTI (J1.2 R4.1), Skywire BBBC (C33.1 C34.1 J6.1 R21.2)
BB_UART1_RX: XBEE and BBBC Header (P9.26 U7.4), CAN (U11.5)
BB_UART1_TX: XBEE and BBBC Header (P9.24 U7.12), CAN (U11.6)
NetC17_1: USB HUB (U2.26), XBEE and BBBC Header (5 pins)
NetD12_5: USB HUB (D12.5 R17.2 U3.5), Skywire BBBC (J6.6)
NetJ6_2: XBEE and BBBC Header (U7.7), Skywire BBBC (J6.2)
NetJ6_3: XBEE and BBBC Header (U7.9), Skywire BBBC (J6.3)
NetJ6_9: XBEE and BBBC Header (R49.2), Skywire BBBC (J6.9 R24.2)
NetJ8_3: XBEE and BBBC Header (J8.3), CAN (R42.1 U11.1 U11.7)
NetJ8_4: XBEE and BBBC Header (J8.4), CAN (R54.2 U10.14)
NetP8_7: XBEE and BBBC Header (P8.7), CAN (R46.1)
NetP8_8: XBEE and BBBC Header (P8.8), Skywire BBBC (Q1.1 R48.1)
NetP8_10: XBEE and BBBC Header (P8.10), CAN (R28.2)
NetP9_19: XBEE and BBBC Header (P9.19), CAN (U10.7)
NetP9_20: XBEE and BBBC Header (P9.20), CAN (U10.9)
NetR11_1: XBEE and BBBC Header (R11.1 U5.6), CAN (U10.6)
NetR12_1: XBEE and BBBC Header (R12.1 U5.5), CAN (U10.10)
SKY_USBD-_N: USB HUB (D12.3 U2.1), Skywire BBBC (J6.8)
SKY_USBD-_P: USB HUB (D12.4 U2.2), Skywire BBBC (J6.7)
